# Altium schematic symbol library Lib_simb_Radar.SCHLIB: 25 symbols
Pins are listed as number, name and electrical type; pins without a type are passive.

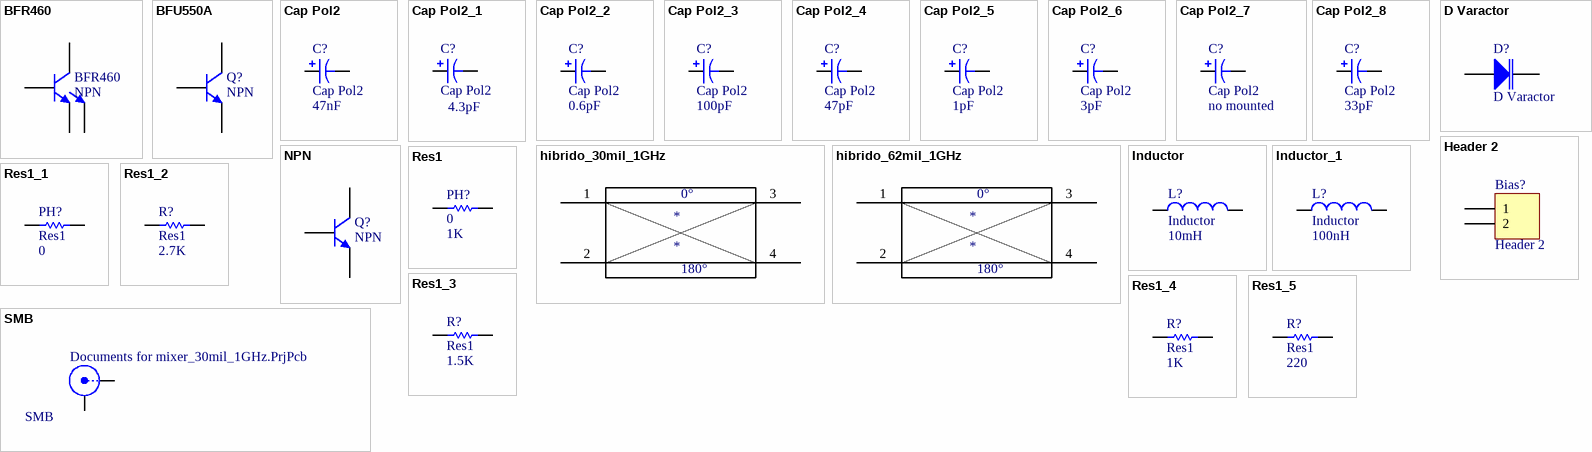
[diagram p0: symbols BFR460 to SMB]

## BFR460
designator BFR460, comment NPN
NPN Bipolar Transistor
footprint SOT-343_N (SOT143, 4-Leads, Body 2.9x1.3mm, Pitch 1.9mm, Lead Span 2.5mm, IPC Medium Density)
pins: 1 E, 2 C, 3 E, 4 B

## BFU550A
designator Q?, comment NPN
NPN Bipolar Transistor
footprint SOT23_N
pins: 1 B, 2 E, 3 C

## Cap Pol2
designator C?  value 47nF
Polarized Capacitor (Axial)
footprint POLAR0.8 (Polarized Capacitor; 2 Leads)
simulation model CAP (Capacitor)
signal-integrity model Cap Pol
footprint 6-0805_N (Chip Resistor, Body 2.0x1.2mm, IPC Medium Density)
pins: 1, 2
1 alternate drawing of the same symbol

## Cap Pol2_1
designator C?, comment Cap Pol2  value 4.3pF
Polarized Capacitor (Axial)
footprint POLAR0.8 (Polarized Capacitor; 2 Leads)
simulation model CAP (Capacitor)
signal-integrity model Cap Pol
footprint 6-0805_N (Chip Resistor, Body 2.0x1.2mm, IPC Medium Density)
pins: 1, 2
1 alternate drawing of the same symbol

## Cap Pol2_2
designator C?, comment Cap Pol2  value 0.6pF
Polarized Capacitor (Axial)
footprint POLAR0.8 (Polarized Capacitor; 2 Leads)
simulation model CAP (Capacitor)
signal-integrity model Cap Pol
footprint 6-0805_N (Chip Resistor, Body 2.0x1.2mm, IPC Medium Density)
pins: 1, 2
1 alternate drawing of the same symbol

## Cap Pol2_3
designator C?, comment Cap Pol2  value 100pF
Polarized Capacitor (Axial)
footprint POLAR0.8 (Polarized Capacitor; 2 Leads)
simulation model CAP (Capacitor)
signal-integrity model Cap Pol
footprint 6-0805_N (Chip Resistor, Body 2.0x1.2mm, IPC Medium Density)
pins: 1, 2
1 alternate drawing of the same symbol

## Cap Pol2_4
designator C?, comment Cap Pol2  value 47pF
Polarized Capacitor (Axial)
footprint POLAR0.8 (Polarized Capacitor; 2 Leads)
simulation model CAP (Capacitor)
signal-integrity model Cap Pol
footprint 6-0805_N (Chip Resistor, Body 2.0x1.2mm, IPC Medium Density)
pins: 1, 2
1 alternate drawing of the same symbol

## Cap Pol2_5
designator C?, comment Cap Pol2  value 1pF
Polarized Capacitor (Axial)
footprint POLAR0.8 (Polarized Capacitor; 2 Leads)
simulation model CAP (Capacitor)
signal-integrity model Cap Pol
footprint 6-0805_N (Chip Resistor, Body 2.0x1.2mm, IPC Medium Density)
pins: 1, 2
1 alternate drawing of the same symbol

## Cap Pol2_6
designator C?, comment Cap Pol2  value 3pF
Polarized Capacitor (Axial)
footprint POLAR0.8 (Polarized Capacitor; 2 Leads)
simulation model CAP (Capacitor)
signal-integrity model Cap Pol
footprint 6-0805_N (Chip Resistor, Body 2.0x1.2mm, IPC Medium Density)
pins: 1, 2
1 alternate drawing of the same symbol

## Cap Pol2_7
designator C?, comment Cap Pol2  value no mounted
Polarized Capacitor (Axial)
footprint POLAR0.8 (Polarized Capacitor; 2 Leads)
simulation model CAP (Capacitor)
signal-integrity model Cap Pol
footprint 6-0805_N (Chip Resistor, Body 2.0x1.2mm, IPC Medium Density)
pins: 1, 2
1 alternate drawing of the same symbol

## Cap Pol2_8
designator C?, comment Cap Pol2  value 33pF
Polarized Capacitor (Axial)
footprint POLAR0.8 (Polarized Capacitor; 2 Leads)
simulation model CAP (Capacitor)
signal-integrity model Cap Pol
footprint 6-0805_N (Chip Resistor, Body 2.0x1.2mm, IPC Medium Density)
pins: 1, 2
1 alternate drawing of the same symbol

## D Varactor
designator D?
Variable Capacitance Diode; Note: Pin 2 is not connected and not drawn.
footprint SOT23_N (SOT23, 3-Leads, Body 2.9x1.3mm, Pitch 0.95mm, Lead Span 2.3mm - Reverse Pinning, IPC Medium Density)
footprint SOT23_L (SOT23, 3-Leads, Body 2.9x1.3mm, Pitch 0.95mm, Lead Span 2.3mm - Reverse Pinning, IPC High Density)
footprint SOT23_M (SOT23, 3-Leads, Body 2.9x1.3mm, Pitch 0.95mm, Lead Span 2.3mm - Reverse Pinning, IPC Low Density)
simulation model BBY31 (Diode)
signal-integrity model D Varactor
footprint 6-0805_N (Chip Resistor, Body 2.0x1.2mm, IPC Medium Density)
pins: 1 A, 2 K

## Header 2
designator Bias?
Header, 2-Pin
footprint HDR1X2 (Connector; Header; 2 Position)
signal-integrity model Connector
pins: 1, 2

## hibrido_30mil_1GHz
designator *
footprint hibrido_30mil_1GHz
pins: 1, 2, 3, 4

## hibrido_62mil_1GHz
designator *
footprint hibrido_62mil_1GHz
footprint hibrido_62mil_1GHz
pins: 1, 2, 3, 4

## Inductor
designator L?  value 10mH
Code_IEC: 1005
footprint 0402-A (Chip Inductor, Body 1.0x0.5mm, IPC High Density)
footprint INDC1608L (Chip Inductor, Body 1.6x0.8mm, IPC High Density)
footprint 2029 (Chip Inductor, Body 2.0x1.2mm, IPC High Density)
footprint 0603 (Chip Inductor, Body 0.6x0.3mm, IPC High Density)
footprint INDC3216 (Chip Inductor, Body 3.2x1.6mm, IPC High Density)
footprint INDC4532 (Chip Inductor, Body 4.5x3.2mm, IPC High Density)
simulation model INDUCTOR (Inductor)
signal-integrity model Inductor
footprint 6-0805_N (Chip Resistor, Body 2.0x1.2mm, IPC Medium Density)
pins: 1, 2

## Inductor_1
designator L?, comment Inductor  value 100nH
Code_IEC: 1005
footprint 0402-A (Chip Inductor, Body 1.0x0.5mm, IPC High Density)
footprint INDC1608L (Chip Inductor, Body 1.6x0.8mm, IPC High Density)
footprint 2029 (Chip Inductor, Body 2.0x1.2mm, IPC High Density)
footprint 0603 (Chip Inductor, Body 0.6x0.3mm, IPC High Density)
footprint INDC3216 (Chip Inductor, Body 3.2x1.6mm, IPC High Density)
footprint INDC4532 (Chip Inductor, Body 4.5x3.2mm, IPC High Density)
simulation model INDUCTOR (Inductor)
signal-integrity model Inductor
footprint 6-0805_N (Chip Resistor, Body 2.0x1.2mm, IPC Medium Density)
pins: 1, 2

## NPN
designator Q?
NPN Bipolar Transistor
footprint TO-226-AA (TO, Flat Index; 3 In-Line, Axial Leads; Body Dia. 4.8mm; Leads 0.55 x 0.51 mm (max))
simulation model NPN
signal-integrity model NPN
footprint SOT23_N (SOT23, 3-Leads, Body 2.9x1.3mm, Pitch 0.95mm, Lead Span 2.3mm - Reverse Pinning, IPC Medium Density)
pins: 1 C, 2 B, 3 E

## Res1
designator PH?, comment 0  value 1K
Resistor
footprint 6-0805_N (Chip Resistor, Body 2.0x1.2mm, IPC Medium Density)
simulation model RESISTOR (Resistor)
signal-integrity model Res
pins: 1, 2

## Res1_1
designator PH?, comment Res1  value 0
Resistor
footprint AXIAL-0.3 (Axial Device, Thru-Hole; 2 Leads; 0.3 in Pin Spacing)
simulation model RESISTOR (Resistor)
signal-integrity model Res
footprint 6-0805_N (Chip Resistor, Body 2.0x1.2mm, IPC Medium Density)
pins: 1, 2

## Res1_2
designator R?, comment Res1  value 2.7K
Resistor
footprint AXIAL-0.3 (Axial Device, Thru-Hole; 2 Leads; 0.3 in Pin Spacing)
simulation model RESISTOR (Resistor)
signal-integrity model Res
footprint 6-0805_N (Chip Resistor, Body 2.0x1.2mm, IPC Medium Density)
pins: 1, 2

## Res1_3
designator R?, comment Res1  value 1.5K
Resistor
footprint AXIAL-0.3 (Axial Device, Thru-Hole; 2 Leads; 0.3 in Pin Spacing)
simulation model RESISTOR (Resistor)
signal-integrity model Res
footprint 6-0805_N (Chip Resistor, Body 2.0x1.2mm, IPC Medium Density)
pins: 1, 2

## Res1_4
designator R?, comment Res1  value 1K
Resistor
footprint AXIAL-0.3 (Axial Device, Thru-Hole; 2 Leads; 0.3 in Pin Spacing)
simulation model RESISTOR (Resistor)
signal-integrity model Res
footprint 6-0805_N (Chip Resistor, Body 2.0x1.2mm, IPC Medium Density)
pins: 1, 2

## Res1_5
designator R?, comment Res1  value 220
Resistor
footprint AXIAL-0.3 (Axial Device, Thru-Hole; 2 Leads; 0.3 in Pin Spacing)
simulation model RESISTOR (Resistor)
signal-integrity model Res
footprint 6-0805_N (Chip Resistor, Body 2.0x1.2mm, IPC Medium Density)
pins: 1, 2

## SMB
designator Documents for mixer_30mil_1GHz.PrjPcb
SMB Straight Connector
footprint SMB_V-RJ45 (Connector; SMB Straight)
signal-integrity model Connector
pins: 1 X, 2 Y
